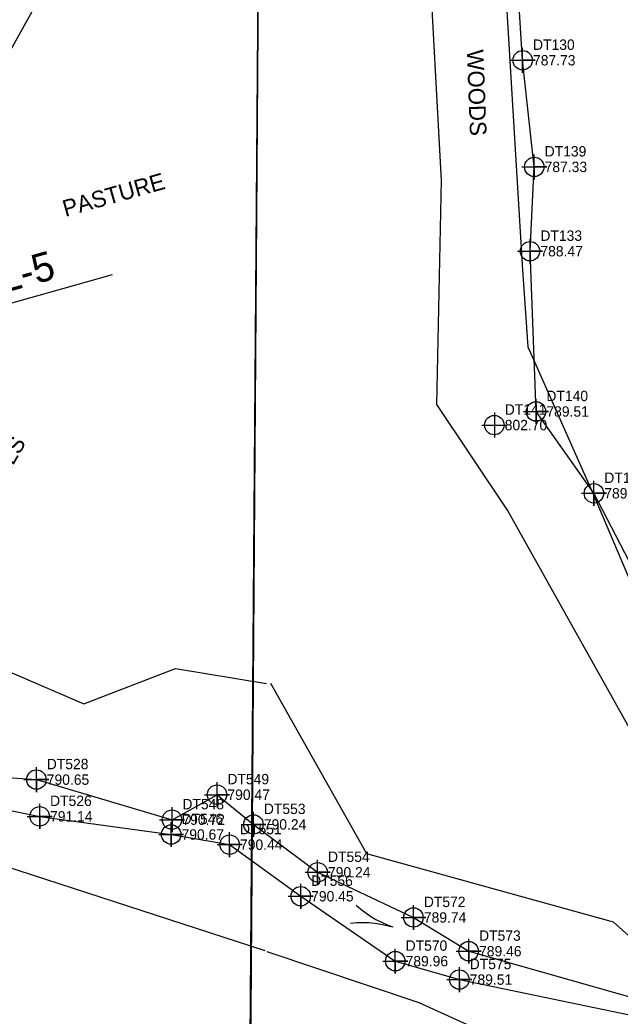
# Model space of a CAD drawing. Extents: x 1316460 to 1321645, y 684173 to 687077.
# Drawn here: x 1319372.4 to 1319517, y 685478.8 to 685718.7 of the extents above; entities that cross this region are included whole.
import ezdxf

# ---------------------------------------------------------------- set-up
doc = ezdxf.new("R2010")
doc.units = 0
for name, color, linetype in [('Exist Earthen Structure Embankment Shoulder Cogo Elevation', 7, 'Continuous'), ('Exist Earthen Structure Embankment Shoulder Cogo Number', 7, 'Continuous'), ('Exist Earthen Structure Embankment Shoulder Cogo Point CELL', 7, 'Continuous'), ('Exist Horizontal Baseline Alignment Station Label', 7, 'Continuous'), ('Exist Hydro Stream Flow Arrow CELL', 7, 'Continuous'), ('Exist Hydro Stream or Body of Water Cogo Elevation', 7, 'Continuous'), ('Exist Hydro Stream or Body of Water Cogo Number', 7, 'Continuous'), ('Exist Hydro Stream or Body of Water Cogo Point CELL', 7, 'Continuous'), ('Exist Hydrographic Water Edge Cogo Elevation', 7, 'Continuous'), ('Exist Other Culture Fence Line', 7, 'Continuous'), ('Exist Other Culture Fence Line Text', 7, 'Continuous'), ('Exist Right of Way Line', 7, 'Continuous'), ('Exist Vegetation Woods Line', 7, 'Continuous'), ('Exist Vegetation Woods Line Text', 7, 'Continuous'), ('Old_Level_59', 7, 'Continuous')]:
    doc.layers.add(name, color=color, linetype=linetype)

# ---------------------------------------------------------------- blocks, each defined once
blk = doc.blocks.new('EXIST HYDRO STREAM FLOW ARROW')
at = {"layer": 'Exist Hydro Stream Flow Arrow CELL'}
blk.add_line((0, 0), (0, 0), dxfattribs=at)
for points in [[(-0.1, 0.04575), (-0.07325, 0.03375), (-0.04475, 0.0245), (-0.0165, 0.01575), (0.01175, 0.0095), (0.041, 0.00475), (0.07075, 0.0015), (0.1, 0)], [(-0.1, -0.04575), (-0.07325, -0.03375), (-0.04475, -0.0245), (-0.0165, -0.01575), (0.01175, -0.0095), (0.041, -0.00475), (0.07075, -0.0015), (0.1, 0)]]:
    blk.add_lwpolyline(points, dxfattribs=at)

msp = doc.modelspace()

# ---------------------------------------------------------------- linework, layer by layer
at = {"layer": 'Exist Earthen Structure Embankment Shoulder Cogo Point CELL'}
for points in [[(1319486.68, 685624.11), (1319486.68, 685621.11)], [(1319483.68, 685621.11), (1319486.68, 685621.11)], [(1319486.68, 685621.11), (1319489.68, 685621.11)], [(1319486.68, 685621.11), (1319486.68, 685618.11)]]:
    msp.add_lwpolyline(points, dxfattribs=at)
msp.add_circle((1319486.68, 685621.11), 2.34, dxfattribs=at)
at = {"layer": 'Exist Horizontal Baseline Alignment Station Label'}
msp.add_line((1319394.63, 685657.26), (1319335.99, 685640.74), dxfattribs=at)
at = {"layer": 'Exist Hydro Stream or Body of Water Cogo Point CELL'}
for points in [[(1319490.49, 685708.97), (1319496.49, 685708.97), (1319493.49, 685708.97), (1319493.49, 685705.97), (1319493.49, 685711.97)], [(1319493.29, 685683.29), (1319499.29, 685683.29), (1319496.29, 685683.29), (1319496.29, 685680.29), (1319496.29, 685686.29)], [(1319492.27, 685662.98), (1319498.27, 685662.98), (1319495.27, 685662.98), (1319495.27, 685659.98), (1319495.27, 685665.98)], [(1319493.71, 685624.38), (1319499.71, 685624.38), (1319496.71, 685624.38), (1319496.71, 685621.38), (1319496.71, 685627.38)], [(1319507.65, 685604.68), (1319513.65, 685604.68), (1319510.65, 685604.68), (1319510.65, 685601.68), (1319510.65, 685607.68)], [(1319373.4, 685535.73), (1319379.4, 685535.73), (1319376.4, 685535.73), (1319376.4, 685532.73), (1319376.4, 685538.73)], [(1319416.9, 685532.1), (1319422.9, 685532.1), (1319419.9, 685532.1), (1319419.9, 685529.1), (1319419.9, 685535.1)], [(1319374.19, 685526.88), (1319380.19, 685526.88), (1319377.19, 685526.88), (1319377.19, 685523.88), (1319377.19, 685529.88)], [(1319406.06, 685526.08), (1319412.06, 685526.08), (1319409.06, 685526.08), (1319409.06, 685523.08), (1319409.06, 685529.08)], [(1319425.67, 685524.94), (1319431.67, 685524.94), (1319428.67, 685524.94), (1319428.67, 685521.94), (1319428.67, 685527.94)], [(1319405.85, 685522.51), (1319411.85, 685522.51), (1319408.85, 685522.51), (1319408.85, 685519.51), (1319408.85, 685525.51)], [(1319419.93, 685520.07), (1319425.93, 685520.07), (1319422.93, 685520.07), (1319422.93, 685517.07), (1319422.93, 685523.07)], [(1319441.12, 685513.41), (1319447.12, 685513.41), (1319444.12, 685513.41), (1319444.12, 685510.41), (1319444.12, 685516.41)], [(1319437.06, 685507.64), (1319443.06, 685507.64), (1319440.06, 685507.64), (1319440.06, 685504.64), (1319440.06, 685510.64)], [(1319464.2, 685502.53), (1319470.2, 685502.53), (1319467.2, 685502.53), (1319467.2, 685499.53), (1319467.2, 685505.53)], [(1319477.5, 685494.41), (1319483.5, 685494.41), (1319480.5, 685494.41), (1319480.5, 685491.41), (1319480.5, 685497.41)], [(1319459.81, 685492.01), (1319465.81, 685492.01), (1319462.81, 685492.01), (1319462.81, 685489.01), (1319462.81, 685495.01)], [(1319475.25, 685487.57), (1319481.25, 685487.57), (1319478.25, 685487.57), (1319478.25, 685484.57), (1319478.25, 685490.57)]]:
    msp.add_lwpolyline(points, dxfattribs=at)
for centre in [(1319493.49, 685708.97), (1319496.29, 685683.29), (1319495.27, 685662.98), (1319496.71, 685624.38), (1319510.65, 685604.68), (1319376.4, 685535.73), (1319419.9, 685532.1), (1319377.19, 685526.88), (1319409.06, 685526.08), (1319428.67, 685524.94), (1319408.85, 685522.51), (1319422.93, 685520.07), (1319444.12, 685513.41), (1319440.06, 685507.64), (1319467.2, 685502.53), (1319480.5, 685494.41), (1319462.81, 685492.01), (1319478.25, 685487.57)]:
    msp.add_circle(centre, 2.34, dxfattribs=at)
at = {"layer": 'Exist Hydrographic Water Edge Cogo Elevation'}
for points in [[(1319493.49, 685708.97), (1319488.34, 685792.08), (1319503.13, 685833.58), (1319542.31, 685920.28), (1319567.85, 685964.41), (1319601.08, 686016.49), (1319606.48, 686046.34)], [(1319496.71, 685624.38), (1319495.27, 685662.98), (1319496.29, 685683.29), (1319493.49, 685708.97)], [(1319315.39, 685642.15), (1319316.13, 685639.47), (1319321.51, 685617.26), (1319325.54, 685603.7), (1319328.94, 685587.06), (1319327, 685577.89), (1319334.14, 685572.31), (1319340.52, 685551.9), (1319356.62, 685537.16), (1319376.4, 685535.73), (1319409.06, 685526.08), (1319419.9, 685532.1), (1319428.67, 685524.94), (1319444.12, 685513.41), (1319467.2, 685502.53), (1319480.5, 685494.41), (1319522.69, 685482.44), (1319536.76, 685479.18), (1319552.73, 685463.94), (1319556.78, 685445.44), (1319572.32, 685412.25), (1319579.73, 685410.53), (1319583.37, 685414.31), (1319593.53, 685423.25)], [(1319307.41, 685629.09), (1319308.12, 685625.61), (1319313.96, 685605.72), (1319322.55, 685586.43), (1319324.96, 685575.24), (1319341.71, 685537.4), (1319355.98, 685531.22), (1319377.19, 685526.88), (1319408.85, 685522.51), (1319422.93, 685520.07), (1319440.06, 685507.64), (1319462.81, 685492.01), (1319478.25, 685487.57), (1319521.18, 685478.7), (1319540.16, 685466.17), (1319547.99, 685448.35)], [(1319605.59, 685425.85), (1319612.23, 685428.51), (1319613.06, 685441.08), (1319570.6, 685493.06), (1319550.06, 685528.84), (1319510.65, 685604.68), (1319496.71, 685624.38)]]:
    msp.add_lwpolyline(points, dxfattribs=at)
at = {"layer": 'Exist Other Culture Fence Line'}
msp.add_lwpolyline([(1319434, 685803.29), (1319421.12, 685801.05), (1319393.69, 685753.82), (1319368.53, 685708.49), (1319345.29, 685668.11), (1319337.7, 685607.39)], dxfattribs=at)
at = {"layer": 'Exist Right of Way Line'}
msp.add_arc((1318364.48, 686300.84), 1160.92, 328.49542, 330.61646, dxfattribs=at)
at = {"layer": 'Exist Vegetation Woods Line'}
for points in [[(1319524.81, 685538.12), (1319489.83, 685600.6), (1319472.82, 685626.06), (1319473.92, 685680.02), (1319471.15, 685731.69), (1319473.42, 685780.64), (1319471.46, 685821.78), (1319478.64, 685851.98), (1319508.33, 685901.22)], [(1319526.59, 685886.99), (1319512.87, 685849.7), (1319500.74, 685824.06), (1319494.16, 685799.69), (1319490.98, 685764.04), (1319489.12, 685730.3), (1319490.97, 685699.54), (1319493.38, 685659.67), (1319494.72, 685639.95), (1319510.38, 685604.71), (1319531.69, 685554.66)], [(1319431.49, 685494.46), (1319362.05, 685517.04), (1319306.58, 685556.19), (1319341.07, 685603.33), (1319354.17, 685568.45), (1319387.8, 685553.99), (1319409.91, 685562.52), (1319431.79, 685558.86)], [(1319432.74, 685558.98), (1319455.93, 685517.97), (1319515.25, 685501.46), (1319563.78, 685458.19), (1319581.38, 685432.58), (1319599.75, 685415.56)], [(1319562.55, 685406.41), (1319524.81, 685456.38), (1319468.6, 685482.01), (1319431.98, 685494.22)]]:
    msp.add_lwpolyline(points, dxfattribs=at)
at = {"layer": 'Old_Level_59'}
for points in [[(1318697.3, 685264.68), (1318675.61, 685496.37), (1319013.72, 685603.72), (1319178.5, 686302.95), (1319290.7, 686462.26), (1319434.76, 686395.34), (1319426.96, 685366.75), (1319230.41, 685144.48), (1318730.33, 685054.78)], [(1319434.63, 686394.86), (1319857.54, 686313.83), (1320008.45, 686252.06), (1320007, 685936.55), (1320002.29, 685545.5), (1319427.33, 685366.56)]]:
    msp.add_lwpolyline(points, close=True, dxfattribs=at)

# ---------------------------------------------------------------- block references
at = {"layer": 'Exist Hydro Stream Flow Arrow CELL', "xscale": 50, "yscale": 50, "rotation": -17.69720277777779}
msp.add_blockref('EXIST HYDRO STREAM FLOW ARROW', (1319457.47, 685501.78), dxfattribs=at)

# ---------------------------------------------------------------- texts
at = {"layer": 'Exist Earthen Structure Embankment Shoulder Cogo Elevation'}
msp.add_text('802.70', height=2.5, dxfattribs=at).set_placement((1319489.18, 685619.86))
at = {"layer": 'Exist Earthen Structure Embankment Shoulder Cogo Number'}
msp.add_text('DT141', height=2.5, dxfattribs=at).set_placement((1319489.18, 685623.61))
at = {"layer": 'Exist Horizontal Baseline Alignment Station Label'}
msp.add_text('-BL-5  ', height=7, rotation=15.7349, dxfattribs=at).set_placement((1319359.38, 685650.28))
at = {"layer": 'Exist Hydro Stream or Body of Water Cogo Elevation'}
for s, p in [('787.73', (1319495.99, 685707.72)), ('787.33', (1319498.79, 685682.04)), ('788.47', (1319497.77, 685661.73)), ('789.51', (1319499.21, 685623.13)), ('789.72', (1319513.15, 685603.43)), ('790.65', (1319378.9, 685534.48)), ('790.47', (1319422.4, 685530.85)), ('791.14', (1319379.69, 685525.63)), ('790.72', (1319411.56, 685524.83)), ('790.24', (1319431.17, 685523.69)), ('790.67', (1319411.35, 685521.26)), ('790.44', (1319425.43, 685518.82)), ('790.24', (1319446.62, 685512.16)), ('790.45', (1319442.56, 685506.39)), ('789.74', (1319469.7, 685501.28)), ('789.46', (1319483, 685493.16)), ('789.96', (1319465.31, 685490.76)), ('789.51', (1319480.75, 685486.32))]:
    msp.add_text(s, height=2.5, dxfattribs=at).set_placement(p)
at = {"layer": 'Exist Hydro Stream or Body of Water Cogo Number'}
for s, p in [('DT130', (1319495.99, 685711.47)), ('DT139', (1319498.79, 685685.79)), ('DT133', (1319497.77, 685665.48)), ('DT140', (1319499.21, 685626.88)), ('DT142', (1319513.15, 685607.18)), ('DT528', (1319378.9, 685538.23)), ('DT549', (1319422.4, 685534.6)), ('DT526', (1319379.69, 685529.38)), ('DT548', (1319411.56, 685528.58)), ('DT553', (1319431.17, 685527.44)), ('DT546', (1319411.35, 685525.01)), ('DT551', (1319425.43, 685522.57)), ('DT554', (1319446.62, 685515.91)), ('DT556', (1319442.56, 685510.14)), ('DT572', (1319469.7, 685505.03)), ('DT573', (1319483, 685496.91)), ('DT570', (1319465.31, 685494.51)), ('DT575', (1319480.75, 685490.07))]:
    msp.add_text(s, height=2.5, dxfattribs=at).set_placement(p)
at = {"layer": 'Exist Other Culture Fence Line Text'}
msp.add_text('PANELS', height=4, rotation=60.1505, dxfattribs=at).set_placement((1319363.5, 685598.58))
at = {"layer": 'Exist Vegetation Woods Line Text'}
for s, rotation, p in [('WOODS', 272.1179, (1319480.05, 685711.48)), ('PASTURE', 15.7349, (1319383.37, 685671.22))]:
    msp.add_text(s, height=4, rotation=rotation, dxfattribs=at).set_placement(p)

doc.saveas('drawing.dxf')
